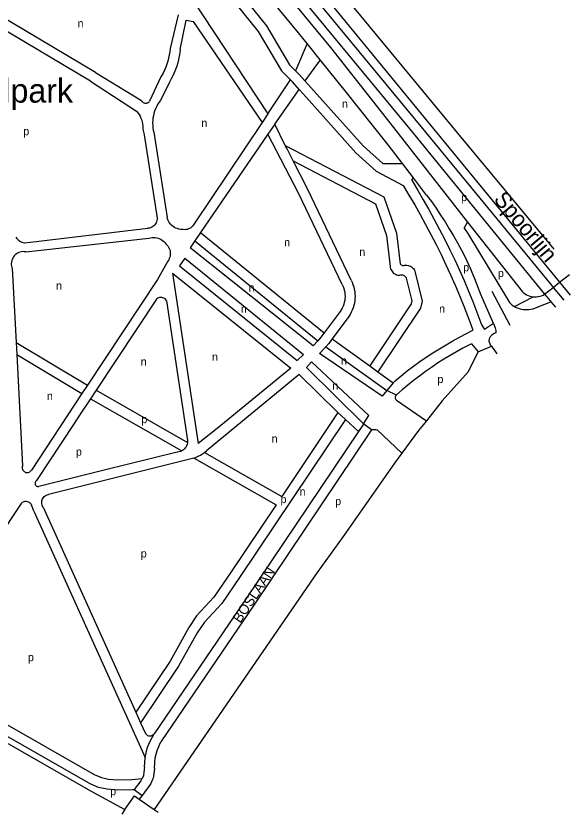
# Model space of a CAD drawing. Extents: x 157155 to 159285, y 385001 to 386651.
# Drawn here: x 159008.3 to 159284.9, y 385000.6 to 385399.2 of the extents above; entities that cross this region are included whole.
import ezdxf

# ---------------------------------------------------------------- set-up
doc = ezdxf.new("R2010")
doc.units = 0
for name, color, linetype in [('BLT_Basislijn', 7, 'Continuous'), ('BLT_Centroide', 7, 'Continuous'), ('BLT_Spoorlijn', 7, 'Continuous'), ('BLT_Sport_parknaam', 7, 'Continuous'), ('BLT_Straatnaam', 7, 'Continuous'), ('BLT_Vlakafsluiter', 7, 'Continuous'), ('BLT_Waternaam_spoorwegen', 7, 'Continuous')]:
    doc.layers.add(name, color=color, linetype=linetype)

msp = doc.modelspace()

# ---------------------------------------------------------------- linework, layer by layer
at = {"layer": 'BLT_Basislijn'}
for p, q in [((159045.49, 385366.59), (158984.59, 385402.96)), ((159048.05, 385370.89), (158997.45, 385401.11)), ((159089.33, 385399.83), (159085.29, 385382.94)), ((159096.79, 385396.41), (159131.19, 385345.95)), ((159153.62, 385385.45), (159147.86, 385371.84)), ((159160.15, 385377.34), (159153.62, 385385.45)), ((159160.15, 385377.34), (159152.57, 385366.82)), ((159172.65, 385361.83), (159160.15, 385377.34)), ((159048.05, 385370.89), (159071, 385356.93)), ((159147.86, 385371.84), (159149.88, 385369.82)), ((159045.49, 385366.59), (159068.52, 385351.64)), ((159080.68, 385368.8), (159075.04, 385356.62)), ((159084.94, 385366.19), (159080.42, 385356.93)), ((159134.13, 385350.33), (159145.33, 385367.3)), ((159145.33, 385367.3), (159146.34, 385366.28)), ((159149.72, 385362.53), (159146.34, 385366.28)), ((159149.88, 385369.82), (159152.57, 385366.82)), ((159152.57, 385366.82), (159155.57, 385363.5)), ((159137.51, 385345.21), (159149.72, 385362.53)), ((159151.84, 385360.17), (159149.72, 385362.53)), ((159134.13, 385350.33), (159131.19, 385345.95)), ((159131.19, 385345.95), (159097.33, 385295.43)), ((159137.51, 385345.21), (159134.08, 385340.19)), ((159142.75, 385334.57), (159137.51, 385345.21)), ((159195.02, 385345.77), (159233.78, 385296.29)), ((159072.32, 385339.81), (159078.74, 385298.27)), ((159077.15, 385341.09), (159083.76, 385298.5)), ((159134.08, 385340.19), (159100.5, 385291.01)), ((159143.62, 385332.81), (159142.75, 385334.57)), ((159146.68, 385326.88), (159143.62, 385332.81)), ((159191.42, 385325.45), (159201.24, 385325.46)), ((159206.72, 385318.32), (159201.24, 385325.46)), ((159188.06, 385321.75), (159201.59, 385314.52)), ((159205.85, 385317.14), (159206.72, 385318.32)), ((159213.27, 385309.77), (159206.72, 385318.32)), ((159232.11, 385293.15), (159233.78, 385296.29)), ((159233.78, 385296.29), (159261.08, 385261.45)), ((159012.83, 385285.92), (159074.15, 385293.2)), ((159100.5, 385291.01), (159097.67, 385286.86)), ((159100.5, 385291.01), (159162.11, 385240.91)), ((159013.18, 385281.39), (159074.7, 385288.23)), ((159097.67, 385286.86), (159095.33, 385283.43)), ((159097.67, 385286.86), (159158.95, 385237.03)), ((159156.7, 385234.54), (159095.33, 385283.43)), ((159084.13, 385276.73), (159078.9, 385267.61)), ((159092.68, 385278.18), (159090.01, 385274.4)), ((159090.01, 385274.4), (159148.73, 385227.15)), ((159092.68, 385278.18), (159151.83, 385230.17)), ((159006.43, 385273.2), (159008.38, 385236.11)), ((159086.52, 385270.79), (159145.56, 385223.28)), ((159086.52, 385270.79), (159099.2, 385185.65)), ((159207.21, 385272.38), (159207.5, 385271.71)), ((159078.9, 385267.61), (159044.04, 385214.8)), ((159245.93, 385261.77), (159254.89, 385244.81)), ((159257.15, 385254.14), (159266.46, 385258.96)), ((159272.21, 385260.25), (159274.89, 385256.98)), ((159078.41, 385257.8), (159048.34, 385212.24)), ((159083.54, 385256.87), (159093.92, 385187.17)), ((159254.13, 385256.89), (159254.59, 385256.12)), ((159269.3, 385254.09), (159275.33, 385256.45)), ((159274.89, 385256.98), (159275.33, 385256.45)), ((159275.33, 385256.45), (159277.56, 385253.72)), ((159169.6, 385250.97), (159162.11, 385240.91)), ((159268.18, 385253.62), (159269.3, 385254.09)), ((159173.43, 385247.77), (159166.09, 385237.88)), ((159246.65, 385245.66), (159242.18, 385242.66)), ((159236.08, 385242.06), (159236.44, 385242.27)), ((159008.38, 385236.11), (159008.7, 385230.1)), ((159008.38, 385236.11), (159044.04, 385214.8)), ((159158.95, 385237.03), (159156.7, 385234.54)), ((159166.09, 385237.88), (159184.9, 385224.39)), ((159235.76, 385235.46), (159239.09, 385231.47)), ((159162.94, 385233.99), (159159.86, 385230.57)), ((159162.94, 385233.99), (159193.45, 385212.11)), ((159234.2, 385221.6), (159239.09, 385231.47)), ((159245.7, 385234.21), (159248.38, 385230.42)), ((159008.7, 385230.1), (159041.28, 385210.62)), ((159008.7, 385230.1), (159011.62, 385174.53)), ((159151.83, 385230.17), (159148.73, 385227.15)), ((159153.27, 385223.56), (159181.83, 385195.45)), ((159184.9, 385224.39), (159188.97, 385221.48)), ((159149.62, 385220.14), (159103.49, 385182.05)), ((159149.62, 385220.14), (159168.96, 385201.1)), ((159188.97, 385221.48), (159196.66, 385215.95)), ((159044.04, 385214.8), (159041.28, 385210.62)), ((159196.66, 385215.95), (159193.45, 385212.11)), ((159197.59, 385217.06), (159196.66, 385215.95)), ((159041.28, 385210.62), (159016.04, 385172.37)), ((159048.34, 385212.24), (159045.58, 385208.06)), ((159048.34, 385212.24), (159093.9, 385186.21)), ((159045.58, 385208.06), (159040.13, 385199.8)), ((159045.58, 385208.06), (159091.12, 385182.04)), ((159198.21, 385207.35), (159213.18, 385197.03)), ((159040.13, 385199.8), (159037.38, 385195.62)), ((159168.96, 385201.1), (159140.96, 385159.25)), ((159168.96, 385201.1), (159172.73, 385197.74)), ((159037.38, 385195.62), (159018.58, 385167.14)), ((159172.73, 385197.74), (159179.3, 385191.66)), ((159181.72, 385195.26), (159179.3, 385191.66)), ((159181.72, 385195.26), (159181.83, 385195.45)), ((159188.58, 385192.43), (159200.92, 385180.88)), ((159088.74, 385181.42), (159052.33, 385172.32)), ((159102.46, 385181.21), (159103.49, 385182.05)), ((159102.46, 385181.21), (159140.96, 385159.25)), ((159097.06, 385178.34), (159024.65, 385160.25)), ((159097.06, 385178.34), (159097.26, 385178.42)), ((159097.26, 385178.42), (159138.18, 385155.08)), ((159052.33, 385172.32), (159045.78, 385170.68)), ((159045.78, 385170.68), (159019.69, 385164.16)), ((159010.88, 385155.73), (158959.48, 385078.25)), ((159017.31, 385151.82), (159016.02, 385155)), ((159017.31, 385151.82), (159072.82, 385028.86)), ((159021.86, 385153.88), (159068.12, 385051.46)), ((158955.81, 385072.71), (159047.39, 385020.39)), ((158951.29, 385066.08), (159045.56, 385012.23)), ((159068.12, 385051.46), (159070.55, 385046.1)), ((159070.55, 385046.1), (159072.77, 385041.19)), ((159072.5, 385024.04), (159072.82, 385028.86)), ((159067.35, 385012.92), (159071.32, 385009.88))]:
    msp.add_line(p, q, dxfattribs=at)
for points in [[(159052.62, 385486.19), (159077.25, 385454.38), (159085.34, 385445.97), (159129.27, 385391.49), (159140.84, 385371.79), (159145.33, 385367.3)], [(159056.57, 385489.25), (159081.04, 385457.65), (159089.1, 385449.28), (159133.4, 385394.34), (159144.82, 385374.87), (159147.86, 385371.84)], [(159153.62, 385385.45), (159149.35, 385390.74), (159070.44, 385486.48)], [(159128.06, 385428.8), (159165.4, 385383.51), (159195.02, 385345.77)], [(159137.44, 385424.52), (159206.62, 385340.75), (159272.21, 385260.25)], [(159099.26, 385419.98), (159096.23, 385407.84), (159134.13, 385350.33)], [(159090.27, 385382.52), (159093.37, 385397.03), (159096.79, 385396.41)], [(159085.29, 385382.94), (159085.12, 385381.34), (159084.86, 385379.75), (159084.53, 385378.18), (159084.12, 385376.62), (159083.64, 385375.09), (159083.08, 385373.58), (159082.44, 385372.11), (159081.73, 385370.66), (159080.95, 385369.26), (159080.68, 385368.8)], [(159090.27, 385382.52), (159090.09, 385380.8), (159089.83, 385379.1), (159089.48, 385377.4), (159089.07, 385375.73), (159088.57, 385374.07), (159087.99, 385372.44), (159087.35, 385370.84), (159086.63, 385369.27), (159085.83, 385367.73), (159084.94, 385366.19)], [(159155.57, 385363.5), (159181.58, 385334.38), (159191.42, 385325.45)], [(159151.84, 385360.17), (159178.02, 385330.85), (159188.06, 385321.75)], [(159201.24, 385325.46), (159194.09, 385334.79), (159172.65, 385361.83)], [(159071, 385356.93), (159071.24, 385356.56), (159071.55, 385356.24), (159071.9, 385355.99), (159072.3, 385355.8), (159072.72, 385355.69), (159073.15, 385355.66), (159073.59, 385355.7), (159074.01, 385355.83), (159074.4, 385356.02), (159074.75, 385356.29), (159075.04, 385356.62)], [(159080.42, 385356.93), (159079.71, 385355.97), (159079.06, 385354.95), (159078.49, 385353.9), (159077.98, 385352.8), (159077.55, 385351.68), (159077.19, 385350.53), (159076.91, 385349.36), (159076.71, 385348.18), (159076.58, 385346.98), (159076.54, 385345.78), (159076.58, 385344.58), (159076.7, 385343.38), (159076.89, 385342.19), (159077.15, 385341.09)], [(159068.52, 385351.64), (159069.17, 385350.83), (159069.75, 385349.98), (159070.26, 385349.08), (159070.71, 385348.14), (159071.08, 385347.17), (159071.38, 385346.18), (159071.54, 385345.44)], [(159071.54, 385345.44), (159071.6, 385344.08), (159071.74, 385342.73), (159071.96, 385341.38), (159072.25, 385340.06), (159072.32, 385339.81)], [(159171.15, 385265.02), (159149.38, 385310.75), (159134.08, 385340.19)], [(159142.75, 385334.57), (159191.88, 385308.95), (159198.2, 385290.66), (159200.09, 385275.48)], [(159175.6, 385267.3), (159153.88, 385312.95), (159146.68, 385326.88)], [(159146.68, 385326.88), (159187.81, 385305.43), (159193.3, 385289.52), (159195.08, 385274.15)], [(159201.59, 385314.52), (159204.5, 385309.71), (159207.34, 385304.86), (159210.11, 385299.97), (159212.82, 385295.04), (159215.45, 385290.07), (159218.01, 385285.07), (159220.49, 385280.03), (159222.91, 385274.95), (159225.26, 385269.84), (159227.53, 385264.7), (159229.73, 385259.53), (159231.85, 385254.33), (159233.9, 385249.09), (159235.87, 385243.83), (159236.44, 385242.27)], [(159205.85, 385317.14), (159208.78, 385312.3), (159211.64, 385307.42), (159214.43, 385302.5), (159217.15, 385297.54), (159219.8, 385292.54), (159222.38, 385287.51), (159224.88, 385282.43), (159227.32, 385277.33), (159229.68, 385272.19), (159231.97, 385267.02), (159234.19, 385261.81), (159236.33, 385256.58), (159238.4, 385251.31), (159240.4, 385246.02), (159240.85, 385244.78), (159242.18, 385242.66)], [(159213.27, 385309.77), (159215.68, 385306.49), (159218.02, 385303.16), (159220.29, 385299.78), (159222.49, 385296.36), (159224.63, 385292.9), (159226.7, 385289.4), (159228.7, 385285.86), (159230.63, 385282.28), (159232.49, 385278.66), (159234.27, 385275.01), (159235.18, 385273.09)], [(159078.74, 385298.27), (159078.73, 385297.65), (159078.65, 385297.04), (159078.49, 385296.44), (159078.26, 385295.87), (159077.95, 385295.33), (159077.58, 385294.84), (159077.14, 385294.4), (159076.65, 385294.02), (159076.12, 385293.71), (159075.56, 385293.47), (159074.96, 385293.3), (159074.35, 385293.21), (159074.15, 385293.2)], [(159091.28, 385292.58), (159090.48, 385292.64), (159089.7, 385292.77), (159088.93, 385292.98), (159088.19, 385293.27), (159087.48, 385293.63), (159086.81, 385294.06), (159086.19, 385294.56), (159085.62, 385295.11), (159085.11, 385295.72), (159084.66, 385296.38), (159084.28, 385297.08), (159083.97, 385297.81), (159083.76, 385298.5)], [(159097.33, 385295.43), (159096.98, 385294.86), (159096.57, 385294.34), (159096.1, 385293.86), (159095.57, 385293.45), (159095, 385293.11), (159094.39, 385292.83), (159093.75, 385292.63), (159093.1, 385292.51), (159092.43, 385292.47), (159091.76, 385292.5), (159091.28, 385292.58)], [(159232.11, 385293.15), (159233.82, 385290.59), (159254.13, 385256.89)], [(159008.3, 385288.81), (159008.65, 385288.24), (159009.06, 385287.73), (159009.53, 385287.26), (159010.06, 385286.86), (159010.62, 385286.52), (159011.23, 385286.25), (159011.86, 385286.06), (159012.52, 385285.94), (159012.83, 385285.92)], [(159074.7, 385288.23), (159075.47, 385288.42), (159076.25, 385288.52), (159077.05, 385288.55), (159077.84, 385288.5), (159078.62, 385288.37), (159079.38, 385288.16), (159080.12, 385287.87), (159080.83, 385287.51), (159081.5, 385287.09), (159082.12, 385286.59), (159082.69, 385286.04), (159083.2, 385285.43)], [(159083.2, 385285.43), (159083.71, 385284.91), (159084.16, 385284.34), (159084.54, 385283.72), (159084.85, 385283.06), (159085.09, 385282.38), (159085.25, 385281.67), (159085.34, 385280.95), (159085.34, 385280.22), (159085.26, 385279.49), (159085.11, 385278.79), (159084.88, 385278.1), (159084.57, 385277.44), (159084.19, 385276.82), (159084.13, 385276.73)], [(159013.18, 385281.39), (159012.49, 385281.48), (159011.79, 385281.49), (159011.1, 385281.42), (159010.42, 385281.27), (159009.76, 385281.04), (159009.14, 385280.74), (159008.55, 385280.37), (159008, 385279.93), (159007.52, 385279.44), (159007.09, 385278.89), (159006.72, 385278.3), (159006.43, 385277.67), (159006.21, 385277.01), (159006.07, 385276.32), (159006.01, 385275.63), (159006.02, 385274.93), (159006.12, 385274.25), (159006.3, 385273.57), (159006.43, 385273.2)], [(159200.09, 385275.48), (159200.31, 385275.18), (159200.59, 385274.93), (159200.92, 385274.75), (159201.27, 385274.64), (159201.65, 385274.6), (159202.02, 385274.65), (159202.16, 385274.69)], [(159202.16, 385274.69), (159202.79, 385274.75), (159203.43, 385274.73), (159204.05, 385274.62), (159204.66, 385274.45), (159205.24, 385274.19), (159205.79, 385273.87), (159206.28, 385273.47), (159206.73, 385273.02), (159207.12, 385272.52), (159207.21, 385272.38)], [(159207.5, 385271.71), (159211.06, 385256.82), (159210.18, 385253.32), (159188.97, 385221.48)], [(159195.08, 385274.15), (159195.16, 385273.54), (159195.32, 385272.95), (159195.56, 385272.38), (159195.86, 385271.84), (159196.24, 385271.35), (159196.67, 385270.91), (159197.15, 385270.54), (159197.69, 385270.22), (159198.25, 385269.98), (159198.85, 385269.82), (159199.46, 385269.73), (159200, 385269.72)], [(159246.65, 385245.66), (159240.4, 385260.17), (159237.31, 385267.88), (159235.18, 385273.09)], [(159175.6, 385267.3), (159176.11, 385266.22), (159176.55, 385265.11), (159176.91, 385263.97), (159177.19, 385262.81), (159177.4, 385261.64), (159177.52, 385260.45), (159177.57, 385259.26), (159177.53, 385258.07), (159177.42, 385256.88), (159177.23, 385255.7), (159176.95, 385254.54), (159176.6, 385253.4), (159176.18, 385252.28), (159175.68, 385251.2), (159175.11, 385250.15), (159174.47, 385249.14), (159173.77, 385248.18), (159173.43, 385247.77)], [(159203.17, 385268.31), (159205.91, 385256.85), (159205.55, 385255.37), (159184.9, 385224.39)], [(159200, 385269.72), (159200.43, 385269.84), (159200.87, 385269.89), (159201.31, 385269.85), (159201.73, 385269.73), (159202.13, 385269.54), (159202.49, 385269.29), (159202.8, 385268.97), (159203.04, 385268.6), (159203.17, 385268.31)], [(159171.15, 385265.02), (159171.58, 385264.1), (159171.93, 385263.15), (159172.21, 385262.18), (159172.41, 385261.18), (159172.53, 385260.18), (159172.57, 385259.17), (159172.53, 385258.16), (159172.41, 385257.15), (159172.21, 385256.16), (159171.93, 385255.19), (159171.58, 385254.24), (159171.15, 385253.32), (159170.65, 385252.44), (159170.09, 385251.6), (159169.6, 385250.97)], [(159083.54, 385256.87), (159083.26, 385257.3), (159082.91, 385257.69), (159082.51, 385258.02), (159082.07, 385258.28), (159081.59, 385258.47), (159081.08, 385258.58), (159080.57, 385258.62), (159080.06, 385258.57), (159079.55, 385258.45), (159079.08, 385258.25), (159078.64, 385257.98), (159078.41, 385257.8)], [(159261.08, 385261.45), (159261.72, 385260.89), (159262.42, 385260.39), (159263.16, 385259.95), (159263.94, 385259.59), (159264.74, 385259.3), (159265.57, 385259.09), (159266.46, 385258.96)], [(159266.46, 385258.96), (159267.27, 385258.91), (159268.13, 385258.93), (159268.98, 385259.04), (159269.82, 385259.22), (159270.64, 385259.49), (159271.42, 385259.82), (159272.21, 385260.25)], [(159254.59, 385256.12), (159255.31, 385255.45), (159256.07, 385254.84), (159256.89, 385254.29), (159257.15, 385254.14)], [(159257.15, 385254.14), (159257.74, 385253.82), (159258.63, 385253.41), (159259.56, 385253.08), (159260.5, 385252.82), (159261.47, 385252.65), (159262.44, 385252.55), (159263.42, 385252.53), (159264.4, 385252.59), (159265.37, 385252.73), (159266.32, 385252.95), (159267.26, 385253.25), (159267.72, 385253.43)], [(159267.72, 385253.43), (159268.18, 385253.62)], [(159246.65, 385245.66), (159247.48, 385243.46), (159247.8, 385242.11), (159247.88, 385240.99)], [(159162.11, 385240.91), (159160.54, 385238.81), (159158.95, 385237.03)], [(159197.59, 385217.06), (159200.6, 385219.53), (159203.65, 385221.94), (159206.76, 385224.28), (159209.91, 385226.56), (159213.11, 385228.77), (159216.36, 385230.92), (159219.65, 385233), (159222.98, 385235.01), (159226.35, 385236.95), (159229.76, 385238.83), (159233.2, 385240.63), (159236.08, 385242.06)], [(159247.88, 385240.99), (159246.74, 385240.39), (159245.87, 385239.8), (159244.99, 385238.95), (159244.54, 385238.02), (159244.38, 385236.74), (159244.62, 385235.88), (159245.1, 385235.01), (159245.7, 385234.21)], [(159166.09, 385237.88), (159164.46, 385235.69), (159162.94, 385233.99)], [(159235.76, 385235.46), (159234.7, 385235.04), (159231.43, 385233.32), (159228.21, 385231.53), (159225.02, 385229.67), (159221.87, 385227.74), (159218.77, 385225.75), (159215.71, 385223.68), (159212.69, 385221.56), (159209.73, 385219.36), (159206.81, 385217.11), (159203.93, 385214.79), (159201.12, 385212.41), (159198.35, 385209.97), (159198.21, 385209.84)], [(159193.45, 385212.11), (159191.09, 385209.27), (159159.86, 385230.57)], [(159145.56, 385223.28), (159108.73, 385193.1), (159099.2, 385185.65)], [(159181.83, 385195.45), (159184.45, 385199.71), (159155.86, 385226.44), (159153.27, 385223.56)], [(159234.2, 385221.6), (159221.04, 385206.91), (159213.18, 385197.03)], [(159198.21, 385209.84), (159197.95, 385209.6), (159197.76, 385209.3), (159197.63, 385208.97), (159197.59, 385208.62), (159197.62, 385208.27), (159197.73, 385207.94), (159197.91, 385207.64), (159198.21, 385207.35)], [(159172.73, 385197.74), (159119.89, 385118.76), (159111.08, 385105.85), (159102.39, 385096.53), (159098.83, 385091.19), (159089.51, 385074.41), (159070.55, 385046.1)], [(159213.18, 385197.03), (159209.26, 385192.11)], [(159179.3, 385191.66), (159123.19, 385108.32), (159077.24, 385040.72)], [(159185.87, 385192.47), (159127.34, 385105.52), (159080.65, 385036.67)], [(159185.87, 385192.47), (159186.34, 385192.64), (159186.83, 385192.74), (159187.33, 385192.75), (159187.83, 385192.69), (159188.31, 385192.55), (159188.58, 385192.43)], [(159209.26, 385192.11), (159200.92, 385180.88)], [(159093.92, 385187.17), (159093.93, 385186.52), (159093.9, 385186.21)], [(159093.9, 385186.21), (159093.87, 385185.87), (159093.73, 385185.23), (159093.51, 385184.62), (159093.22, 385184.04), (159092.85, 385183.5), (159092.43, 385183.01), (159091.95, 385182.57), (159091.42, 385182.2), (159091.12, 385182.04)], [(159200.92, 385180.88), (159197.24, 385175.93), (159171.64, 385139.21), (159158.74, 385121.24), (159077.24, 385002.93)], [(159091.12, 385182.04), (159090.84, 385181.89), (159090.23, 385181.66), (159089.6, 385181.5), (159088.96, 385181.42), (159088.74, 385181.42)], [(159097.26, 385178.42), (159098.22, 385178.78), (159099.35, 385179.29), (159100.45, 385179.88), (159101.5, 385180.53), (159102.46, 385181.21)], [(159011.62, 385174.53), (159011.49, 385174.1), (159011.45, 385173.66), (159011.48, 385173.22), (159011.59, 385172.79), (159011.78, 385172.39), (159012.03, 385172.02), (159012.35, 385171.71), (159012.71, 385171.46), (159013.12, 385171.28), (159013.55, 385171.18), (159013.99, 385171.15), (159014.43, 385171.21), (159014.86, 385171.34), (159015.25, 385171.55), (159015.6, 385171.82), (159015.9, 385172.15), (159016.04, 385172.37)], [(159018.58, 385167.14), (159018.31, 385166.9), (159018.1, 385166.61), (159017.96, 385166.27), (159017.89, 385165.92), (159017.91, 385165.55), (159018, 385165.2), (159018.17, 385164.88), (159018.4, 385164.61), (159018.69, 385164.39), (159019.02, 385164.24), (159019.38, 385164.16), (159019.69, 385164.16)], [(159021.86, 385153.88), (159021.58, 385154.38), (159021.37, 385154.92), (159021.23, 385155.47), (159021.18, 385156.05), (159021.2, 385156.62), (159021.3, 385157.18), (159021.48, 385157.73), (159021.73, 385158.25), (159022.06, 385158.72), (159022.44, 385159.15), (159022.88, 385159.52), (159023.37, 385159.82), (159023.9, 385160.05), (159024.45, 385160.21), (159024.65, 385160.25)], [(159010.88, 385155.73), (159011.21, 385156.08), (159011.6, 385156.38), (159012.04, 385156.61), (159012.5, 385156.77), (159012.99, 385156.85), (159013.48, 385156.85), (159013.96, 385156.77), (159014.43, 385156.61), (159014.86, 385156.38), (159015.25, 385156.08), (159015.59, 385155.72), (159015.87, 385155.32), (159016.02, 385155)], [(159138.18, 385155.08), (159115.75, 385121.56), (159107.16, 385108.98), (159098.46, 385099.65), (159094.56, 385093.8), (159085.24, 385077.02), (159068.12, 385051.46)], [(158951.29, 385066.08), (158952.55, 385068.82), (159045.17, 385015.91)], [(159072.77, 385041.19), (159072.99, 385040.79), (159073.27, 385040.44), (159073.62, 385040.14), (159074.01, 385039.91), (159074.43, 385039.74), (159074.88, 385039.66), (159075.33, 385039.65), (159075.78, 385039.73), (159076.21, 385039.88), (159076.61, 385040.1), (159076.96, 385040.39), (159077.24, 385040.72)], [(159072.82, 385028.86), (159072.93, 385029.67), (159074.02, 385033.96), (159075.27, 385037.05), (159077.24, 385040.72)], [(159077.47, 385023.52), (159077.85, 385028.73), (159078.78, 385032.4), (159079.9, 385035.17), (159080.65, 385036.67)], [(159072.5, 385024.04), (159072.23, 385021.47), (159071.94, 385019.94), (159071.33, 385018.45)], [(159077.47, 385023.52), (159077.18, 385020.75), (159076.76, 385018.52), (159076.5, 385017.89)], [(159047.39, 385020.39), (159050.96, 385018.88), (159054.54, 385018.1), (159059.16, 385017.76), (159066.14, 385017.81), (159071.33, 385018.45)], [(159045.17, 385015.91), (159049.44, 385014.09), (159053.82, 385013.14), (159058.99, 385012.76), (159066.46, 385012.81), (159067.35, 385012.92)], [(159071.33, 385018.45), (159071.23, 385018.2), (159070.6, 385017.18), (159067.35, 385012.92)], [(159076.5, 385017.89), (159075.7, 385015.93), (159074.73, 385014.35), (159074.07, 385013.48)], [(159045.56, 385012.23), (159062.7, 385002.81)], [(159074.07, 385013.48), (159071.32, 385009.88)], [(159062.7, 385002.81), (159067.43, 385009.72), (159069.9, 385008.02)], [(159069.9, 385008.02), (159077.25, 385002.93)]]:
    msp.add_lwpolyline(points, dxfattribs=at)
at = {"layer": 'BLT_Spoorlijn'}
for p, q in [((159216.74, 385342.82), (159279.67, 385266.18)), ((159275.43, 385264.95), (159276.5, 385263.66)), ((159276.5, 385263.66), (159281.81, 385257.27)), ((159279.67, 385266.18), (159284.88, 385259.83))]:
    msp.add_line(p, q, dxfattribs=at)
for points in [[(159141.3, 385427.7), (159210.48, 385343.93)], [(159147.93, 385426.96), (159216.74, 385342.82)], [(159156.57, 385428.25), (159228.69, 385340.61)], [(159210.48, 385343.93), (159275.43, 385264.95)], [(159228.69, 385340.61), (159276.86, 385282.68)]]:
    msp.add_lwpolyline(points, dxfattribs=at)
at = {"layer": 'BLT_Vlakafsluiter'}
for p, q in [((159279.67, 385266.18), (159284.63, 385270.12)), ((159272.21, 385260.25), (159276.5, 385263.66)), ((159276.5, 385263.66), (159279.67, 385266.18)), ((159239.09, 385231.47), (159245.7, 385234.21)), ((159198.21, 385209.84), (159193.45, 385212.11)), ((159185.87, 385192.47), (159181.83, 385195.45)), ((159071.32, 385009.88), (159069.9, 385008.02)), ((159062.7, 385002.81), (159061.2, 385000.62)), ((159077.24, 385002.93), (159079.23, 385001.56))]:
    msp.add_line(p, q, dxfattribs=at)

# ---------------------------------------------------------------- texts
at = {"layer": 'BLT_Centroide'}
for s, p in [('n', (159039.06, 385393.54)), ('n', (159171.02, 385353.38)), ('n', (159100.88, 385343.77)), ('p', (159011.97, 385339.64)), ('p', (159230.53, 385306.72)), ('n', (159142.2, 385284.17)), ('n', (159179.67, 385279.37)), ('p', (159231.55, 385271.68)), ('p', (159248.85, 385268.79)), ('n', (159028.35, 385262.53)), ('n', (159124.42, 385261.58)), ('n', (159120.58, 385251.01)), ('n', (159219.54, 385251.01)), ('n', (159070.61, 385224.57)), ('n', (159106.17, 385226.98)), ('n', (159170.54, 385225.05)), ('p', (159218.7, 385215.83)), ('n', (159166.22, 385212.56)), ('n', (159023.76, 385207.43)), ('p', (159070.93, 385195.83)), ('n', (159135.95, 385186.12)), ('p', (159038.29, 385179.59)), ('n', (159149.88, 385159.69)), ('p', (159140.37, 385155.89)), ('p', (159167.66, 385154.88)), ('p', (159070.62, 385128.76)), ('p', (159014.3, 385076.95)), ('p', (159055.36, 385010.04))]:
    msp.add_text(s, height=4, dxfattribs=at).set_placement(p)
at = {"layer": 'BLT_Sport_parknaam'}
msp.add_text('Philips de Jongh Wandelpark', height=12, rotation=0.0206, dxfattribs=at).set_placement((158829, 385355.85))
at = {"layer": 'BLT_Straatnaam'}
msp.add_text('BOSLAAN', height=5, rotation=56.056, dxfattribs=at).set_placement((159120.27, 385095.65))
at = {"layer": 'BLT_Waternaam_spoorwegen'}
msp.add_text('Spoorlijn', height=8, rotation=309.8574, dxfattribs=at).set_placement((159246.39, 385307.43))

doc.saveas('drawing.dxf')
